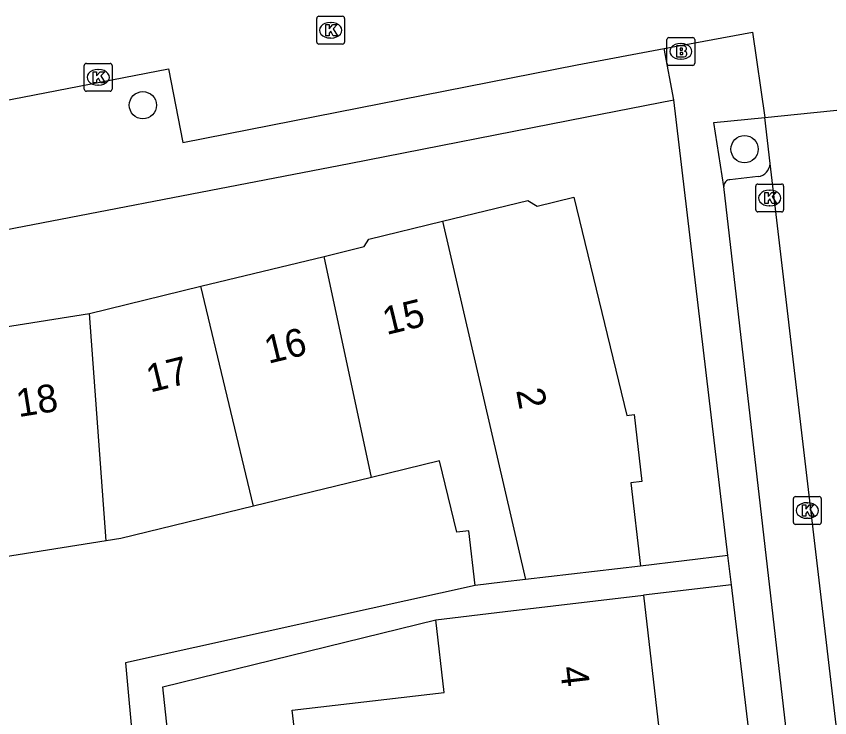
# Model space of a CAD drawing. Extents: x 162250 to 162654, y 380744 to 381605.
# Drawn here: x 162419.71 to 162448.96, y 381100.24 to 381125.44 of the extents above; entities that cross this region are included whole.
import ezdxf

# ---------------------------------------------------------------- set-up
doc = ezdxf.new("R2010")
doc.units = 0
for name, color, linetype in [('IMGEO_Boom', 7, 'Continuous'), ('IMGEO_Brandkraan', 7, 'Continuous'), ('IMGEO_Kolk', 7, 'Continuous'), ('IMGEO_Pand', 7, 'Continuous'), ('IMGEO_Pand_nummerreeks', 7, 'Continuous'), ('IMGEO_Parkeervlak_open', 7, 'Continuous'), ('IMGEO_Rijbaan_lokaal_open', 7, 'Continuous'), ('IMGEO_Voetpad_open', 7, 'Continuous')]:
    doc.layers.add(name, color=color, linetype=linetype)

msp = doc.modelspace()

# ---------------------------------------------------------------- linework, layer by layer
at = {"layer": 'IMGEO_Boom'}
for centre in [(162424.267, 381122.24), (162445.894, 381120.662)]:
    msp.add_circle(centre, 0.489, dxfattribs=at)
at = {"layer": 'IMGEO_Brandkraan'}
for p, q in [((162443.103, 381123.747), (162443.103, 381124.599)), ((162443.178, 381124.673), (162444.03, 381124.673)), ((162444.104, 381124.599), (162444.104, 381123.747)), ((162443.591, 381124.453), (162443.616, 381124.453)), ((162443.614, 381123.893), (162443.589, 381123.893)), ((162444.03, 381123.673), (162443.178, 381123.673))]:
    msp.add_line(p, q, dxfattribs=at)
for points in [[(162443.103, 381123.747), (162443.103, 381124.599)], [(162443.178, 381124.673), (162444.03, 381124.673)], [(162444.104, 381124.599), (162444.104, 381123.747)], [(162443.451, 381124.373), (162443.451, 381123.973), (162443.664, 381123.973)], [(162443.682, 381124.373), (162443.451, 381124.373)], [(162443.63, 381124.292), (162443.576, 381124.292), (162443.576, 381124.216)], [(162443.576, 381124.216), (162443.629, 381124.216)], [(162443.638, 381124.14), (162443.576, 381124.14), (162443.576, 381124.059)], [(162443.576, 381124.059), (162443.638, 381124.059)], [(162444.03, 381123.673), (162443.178, 381123.673)]]:
    msp.add_lwpolyline(points, dxfattribs=at)
for centre, radius, start, end in [((162443.18, 381124.597), 0.0765, 91.552, 178.448), ((162443.18, 381124.597), 0.0765, 91.552, 178.448), ((162444.028, 381124.597), 0.0765, 1.552, 88.448), ((162444.028, 381124.597), 0.0765, 1.552, 88.448), ((162443.631, 381124.254), 0.0379, 267.8285, 90.9355), ((162443.686, 381124.228), 0.145, 59.4692, 91.5367), ((162443.711, 381124.275), 0.0922, 285.5137, 58.1501), ((162443.716, 381124.083), 0.105, 301.3115, 78.989), ((162443.639, 381124.099), 0.0404, 269.8759, 90.5077), ((162443.67, 381124.224), 0.251, 268.6676, 293.5347), ((162443.18, 381123.749), 0.0765, 181.552, 268.448), ((162443.18, 381123.749), 0.0765, 181.552, 268.448), ((162444.028, 381123.749), 0.0765, 271.552, 358.448), ((162444.028, 381123.749), 0.0765, 271.552, 358.448)]:
    msp.add_arc(centre, radius, start, end, dxfattribs=at)
for centre, major_axis, ratio, start_param, end_param in [((162443.59, 381124.173), (-0.387, 0.002), 0.722429, 4.712389, 7.853982), ((162443.615, 381124.173), (-0.39, 0.002), 0.717154, 1.570796, 4.712389)]:
    msp.add_ellipse(centre, major_axis=major_axis, ratio=ratio, start_param=start_param, end_param=end_param, dxfattribs=at)
at = {"layer": 'IMGEO_Kolk'}
for p, q in [((162430.516, 381124.509), (162430.516, 381125.361)), ((162430.591, 381125.435), (162431.443, 381125.435)), ((162431.517, 381125.361), (162431.517, 381124.509)), ((162431.004, 381125.215), (162431.029, 381125.215)), ((162431.027, 381124.655), (162431.002, 381124.655)), ((162431.443, 381124.435), (162430.591, 381124.435)), ((162422.16, 381122.817), (162422.16, 381123.669)), ((162422.235, 381123.743), (162423.087, 381123.743)), ((162423.161, 381123.669), (162423.161, 381122.817)), ((162422.648, 381123.523), (162422.673, 381123.523)), ((162423.087, 381122.743), (162422.235, 381122.743)), ((162422.671, 381122.963), (162422.646, 381122.963)), ((162446.298, 381118.484), (162446.298, 381119.336)), ((162446.373, 381119.41), (162447.225, 381119.41)), ((162447.299, 381119.336), (162447.299, 381118.484)), ((162446.786, 381119.19), (162446.811, 381119.19)), ((162446.809, 381118.63), (162446.784, 381118.63)), ((162447.225, 381118.41), (162446.373, 381118.41)), ((162447.651, 381107.257), (162447.651, 381108.109)), ((162447.726, 381108.183), (162448.578, 381108.183)), ((162448.652, 381108.109), (162448.652, 381107.257)), ((162448.139, 381107.963), (162448.164, 381107.963)), ((162448.162, 381107.403), (162448.137, 381107.403)), ((162448.578, 381107.183), (162447.726, 381107.183))]:
    msp.add_line(p, q, dxfattribs=at)
for points in [[(162430.516, 381124.509), (162430.516, 381125.361)], [(162430.591, 381125.435), (162431.443, 381125.435)], [(162431.517, 381125.361), (162431.517, 381124.509)], [(162430.837, 381125.135), (162430.96, 381125.135), (162430.96, 381124.984), (162431.09, 381125.135), (162431.254, 381125.135), (162431.108, 381124.984), (162431.261, 381124.735), (162431.109, 381124.735), (162431.024, 381124.899), (162430.96, 381124.832), (162430.96, 381124.735), (162430.837, 381124.735), (162430.837, 381125.135)], [(162431.443, 381124.435), (162430.591, 381124.435)], [(162422.16, 381122.817), (162422.16, 381123.669)], [(162422.235, 381123.743), (162423.087, 381123.743)], [(162423.161, 381123.669), (162423.161, 381122.817)], [(162422.481, 381123.443), (162422.604, 381123.443), (162422.604, 381123.292), (162422.734, 381123.443), (162422.898, 381123.443), (162422.752, 381123.292), (162422.905, 381123.043), (162422.753, 381123.043), (162422.668, 381123.207), (162422.604, 381123.14), (162422.604, 381123.043), (162422.481, 381123.043), (162422.481, 381123.443)], [(162423.087, 381122.743), (162422.235, 381122.743)], [(162446.298, 381118.484), (162446.298, 381119.336)], [(162446.373, 381119.41), (162447.225, 381119.41)], [(162447.299, 381119.336), (162447.299, 381118.484)], [(162446.619, 381119.11), (162446.742, 381119.11), (162446.742, 381118.959), (162446.872, 381119.11), (162447.036, 381119.11), (162446.89, 381118.959), (162447.043, 381118.71), (162446.891, 381118.71), (162446.806, 381118.874), (162446.742, 381118.807), (162446.742, 381118.71), (162446.619, 381118.71), (162446.619, 381119.11)], [(162447.225, 381118.41), (162446.373, 381118.41)], [(162447.651, 381107.257), (162447.651, 381108.109)], [(162447.726, 381108.183), (162448.578, 381108.183)], [(162448.652, 381108.109), (162448.652, 381107.257)], [(162447.972, 381107.883), (162448.095, 381107.883), (162448.095, 381107.732), (162448.225, 381107.883), (162448.389, 381107.883), (162448.243, 381107.732), (162448.396, 381107.483), (162448.244, 381107.483), (162448.159, 381107.647), (162448.095, 381107.58), (162448.095, 381107.483), (162447.972, 381107.483), (162447.972, 381107.883)], [(162448.578, 381107.183), (162447.726, 381107.183)]]:
    msp.add_lwpolyline(points, dxfattribs=at)
for centre, start, end in [((162430.593, 381125.359), 91.552, 178.448), ((162430.593, 381125.359), 91.552, 178.448), ((162431.441, 381125.359), 1.552, 88.448), ((162431.441, 381125.359), 1.552, 88.448), ((162430.593, 381124.511), 181.552, 268.448), ((162430.593, 381124.511), 181.552, 268.448), ((162431.441, 381124.511), 271.552, 358.448), ((162431.441, 381124.511), 271.552, 358.448), ((162422.237, 381123.667), 91.552, 178.448), ((162422.237, 381123.667), 91.552, 178.448), ((162423.085, 381123.667), 1.552, 88.448), ((162423.085, 381123.667), 1.552, 88.448), ((162422.237, 381122.819), 181.552, 268.448), ((162422.237, 381122.819), 181.552, 268.448), ((162423.085, 381122.819), 271.552, 358.448), ((162423.085, 381122.819), 271.552, 358.448), ((162446.375, 381119.334), 91.552, 178.448), ((162446.375, 381119.334), 91.552, 178.448), ((162447.223, 381119.334), 1.552, 88.448), ((162447.223, 381119.334), 1.552, 88.448), ((162446.375, 381118.486), 181.552, 268.448), ((162446.375, 381118.486), 181.552, 268.448), ((162447.223, 381118.486), 271.552, 358.448), ((162447.223, 381118.486), 271.552, 358.448), ((162447.728, 381108.107), 91.552, 178.448), ((162447.728, 381108.107), 91.552, 178.448), ((162448.576, 381108.107), 1.552, 88.448), ((162448.576, 381108.107), 1.552, 88.448), ((162447.728, 381107.259), 181.552, 268.448), ((162447.728, 381107.259), 181.552, 268.448), ((162448.576, 381107.259), 271.552, 358.448), ((162448.576, 381107.259), 271.552, 358.448)]:
    msp.add_arc(centre, 0.0765, start, end, dxfattribs=at)
for centre, major_axis, ratio, start_param, end_param in [((162431.003, 381124.935), (-0.387, 0.002), 0.722429, 4.712389, 7.853982), ((162431.028, 381124.935), (-0.39, 0.002), 0.717154, 1.570796, 4.712389), ((162422.647, 381123.243), (-0.387, 0.002), 0.722429, 4.712389, 7.853982), ((162422.672, 381123.243), (-0.39, 0.002), 0.717154, 1.570796, 4.712389), ((162446.785, 381118.91), (-0.387, 0.002), 0.722429, 4.712389, 7.853982), ((162446.81, 381118.91), (-0.39, 0.002), 0.717154, 1.570796, 4.712389), ((162448.138, 381107.683), (-0.387, 0.002), 0.722429, 4.712389, 7.853982), ((162448.163, 381107.683), (-0.39, 0.002), 0.717154, 1.570796, 4.712389)]:
    msp.add_ellipse(centre, major_axis=major_axis, ratio=ratio, start_param=start_param, end_param=end_param, dxfattribs=at)
at = {"layer": 'IMGEO_Pand'}
for points in [[(162435.035, 381118.074), (162438.102, 381118.819), (162438.44, 381118.614), (162439.76, 381118.935), (162441.665, 381111.099), (162441.924, 381111.129), (162442.207, 381108.723), (162441.806, 381108.676), (162442.157, 381105.689)], [(162430.777, 381116.813), (162432.222, 381117.164), (162432.383, 381117.429), (162435.035, 381118.074)], [(162435.035, 381118.074), (162438.018, 381105.204)], [(162426.349, 381115.736), (162430.777, 381116.813)], [(162432.479, 381108.87), (162430.777, 381116.813)], [(162422.345, 381114.763), (162426.349, 381115.736)], [(162428.24, 381107.839), (162426.349, 381115.736)], [(162417.432, 381113.976), (162422.345, 381114.763)], [(162422.941, 381106.596), (162422.345, 381114.763)], [(162436.213, 381104.992), (162435.982, 381106.957), (162435.55, 381106.906), (162434.927, 381109.465), (162432.479, 381108.87)], [(162432.479, 381108.87), (162428.24, 381107.839)], [(162428.24, 381107.839), (162423.477, 381106.681), (162422.941, 381106.596)], [(162422.941, 381106.596), (162418.713, 381105.929)], [(162442.157, 381105.689), (162438.018, 381105.204)], [(162438.018, 381105.204), (162437.192, 381105.107), (162436.213, 381104.992)], [(162434.792, 381103.761), (162437.291, 381104.054), (162442.256, 381104.637)], [(162442.256, 381104.637), (162442.854, 381099.538)], [(162429.914, 381098.061), (162429.626, 381100.509), (162435.098, 381101.151), (162434.792, 381103.761)]]:
    msp.add_lwpolyline(points, dxfattribs=at)
at = {"layer": 'IMGEO_Parkeervlak_open'}
msp.add_lwpolyline([(162446.386, 381119.676), (162445.371, 381119.566)], dxfattribs=at)
for centre, radius, start, end in [((162446.318, 381120.164), 0.492, 277.9282, 357.4755), ((162445.379, 381119.334), 0.232, 92.012, 182.1755)]:
    msp.add_arc(centre, radius, start, end, dxfattribs=at)
at = {"layer": 'IMGEO_Rijbaan_lokaal_open'}
for points in [[(162446.621, 381121.794), (162450.271, 381122.166)], [(162446.81, 381120.142), (162446.621, 381121.794)], [(162449.542, 381096.926), (162446.81, 381120.142)]]:
    msp.add_lwpolyline(points, dxfattribs=at)
at = {"layer": 'IMGEO_Voetpad_open'}
for points in [[(162443.007, 381124.274), (162446.181, 381124.863), (162446.621, 381121.794)], [(162401.595, 381114.357), (162401.509, 381116.144), (162410.022, 381117.819), (162409.493, 381120.503), (162425.183, 381123.553), (162425.704, 381120.904), (162439.872, 381123.692), (162443.007, 381124.274)], [(162443.348, 381122.437), (162443.007, 381124.274)], [(162401.595, 381114.357), (162431.678, 381120.144), (162440.223, 381121.823), (162443.348, 381122.437)], [(162445.298, 381106.063), (162443.348, 381122.437)], [(162445.147, 381119.325), (162444.787, 381121.617), (162446.621, 381121.794)], [(162447.671, 381097.419), (162445.147, 381119.325)], [(162445.298, 381106.063), (162442.157, 381105.689)], [(162445.423, 381105.014), (162445.298, 381106.063)], [(162436.213, 381104.992), (162423.638, 381102.209), (162423.934, 381099.061)], [(162445.423, 381105.014), (162442.256, 381104.637)], [(162460.106, 380980.583), (162457.834, 381000), (162450.879, 381059.205), (162445.423, 381105.014)], [(162429.65, 381057.925), (162426.098, 381090.941), (162424.979, 381101.344), (162434.792, 381103.761)]]:
    msp.add_lwpolyline(points, dxfattribs=at)

# ---------------------------------------------------------------- texts
at = {"layer": 'IMGEO_Pand_nummerreeks'}
for s, rotation, p in [('15', 13.6645, (162433.021, 381113.983)), ('16', 13.6646, (162428.775, 381112.95)), ('17', 13.6646, (162424.528, 381111.918)), ('18', 9.0526, (162419.795, 381111.035)), ('2', 280.2573, (162437.682, 381112.002)), ('4', 276.6903, (162439.257, 381102.048))]:
    msp.add_text(s, height=1, rotation=rotation, dxfattribs=at).set_placement(p)

doc.saveas('drawing.dxf')
